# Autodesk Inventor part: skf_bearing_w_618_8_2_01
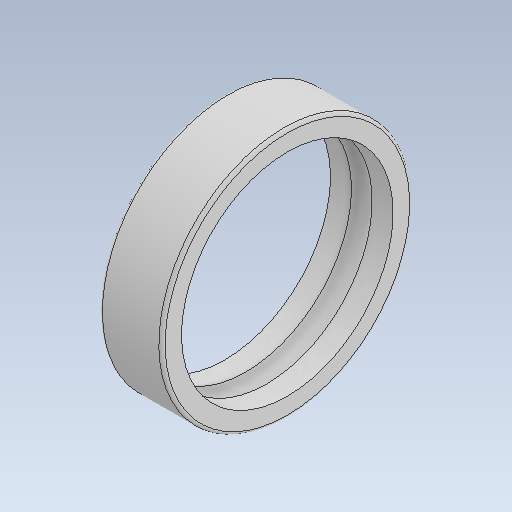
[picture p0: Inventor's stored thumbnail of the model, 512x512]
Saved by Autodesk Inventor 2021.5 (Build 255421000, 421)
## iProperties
Created: 2023-11
Part Number: skf_bearing_w_618_8_2_01
Checked By: TraceParts S.A.
Material: Generic
Catalog Web Link: www.traceparts.com
Document SubType Name: Modeling
Designer: TraceParts
Density: 1 g/cm^3
Appearance: Default
Company: TraceParts S.A.
Author: TraceParts
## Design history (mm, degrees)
feature "skf_bearing_w_618_8_2_01.ipt"
body "Solid1"
